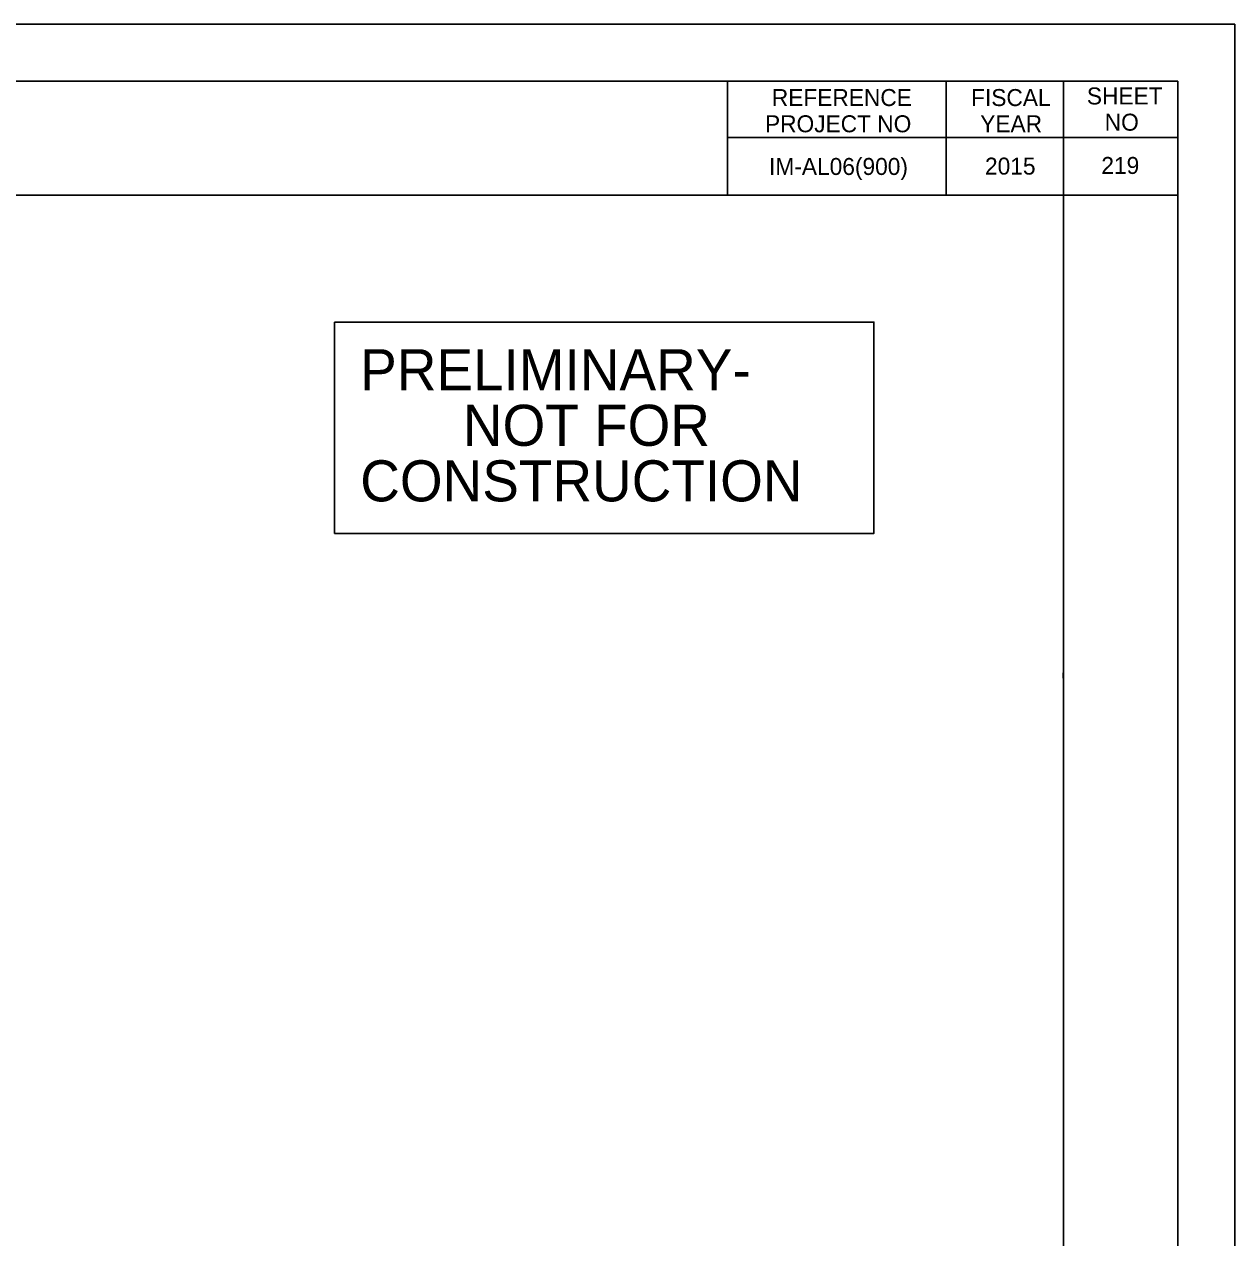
# Model space of a CAD drawing. Extents: x 515543 to 517243, y 660510 to 662861.
# Drawn here: x 516712 to 517243, y 662329 to 662861 of the extents above; entities that cross this region are included whole.
import ezdxf

# ---------------------------------------------------------------- set-up
doc = ezdxf.new("R2010")
doc.units = 0
for name, color, linetype in [('1', 7, 'Continuous'), ('2', 7, 'Continuous'), ('ANNO-SHT', 7, 'Continuous'), ('Level 6', 7, 'Continuous'), ('Level 62', 7, 'Continuous'), ('SHT-BDR', 7, 'Continuous'), ('SHT-BNDRY', 7, 'Continuous')]:
    doc.layers.add(name, color=color, linetype=linetype)

msp = doc.modelspace()

# ---------------------------------------------------------------- linework, layer by layer
at = {"layer": '1'}
msp.add_lwpolyline([(516847.95, 662730.18), (517084.37, 662730.18), (517084.37, 662637.55), (516847.95, 662637.55)], close=True, dxfattribs=at)
at = {"layer": '2'}
msp.add_lwpolyline([(517167.33, 662576.47), (517167.38, 662571.47)], dxfattribs=at)
msp.add_lwpolyline([(517167.33, 662576.47), (517167.38, 662571.47)], dxfattribs=at)
at = {"layer": 'Level 6'}
for p, q in [((517020.23, 662835.72), (517020.23, 662785.77)), ((517116.05, 662810.73), (517116.05, 662835.73)), ((517167.5, 662811.38), (517167.5, 662835.73)), ((517217.52, 662811.02), (517020.23, 662811.02)), ((517116.05, 662810.73), (517116.05, 662785.77)), ((517167.5, 662811.38), (517167.5, 662785.77)), ((517217.52, 662785.77), (517026.28, 662785.77))]:
    msp.add_line(p, q, dxfattribs=at)
at = {"layer": 'Level 62'}
msp.add_lwpolyline([(515542.51, 661760.72), (517242.52, 661760.72), (517242.52, 662860.72), (515542.51, 662860.72)], close=True, dxfattribs=at)
at = {"layer": 'SHT-BDR'}
msp.add_lwpolyline([(515667.5, 661835.77), (517167.5, 661835.77), (517167.5, 662785.77), (515667.5, 662785.77)], close=True, dxfattribs=at)
at = {"layer": 'SHT-BNDRY'}
msp.add_lwpolyline([(515605.01, 661785.72), (517217.52, 661785.72), (517217.52, 662835.72), (515605.01, 662835.72)], close=True, dxfattribs=at)

# ---------------------------------------------------------------- texts
at = {"layer": '1'}
for s, p in [('PRELIMINARY-', (516859.13, 662700.31)), ('NOT FOR', (516904.16, 662675.95)), ('CONSTRUCTION', (516859.16, 662651.6))]:
    msp.add_text(s, height=18, dxfattribs=at).set_placement(p)
at = {"layer": 'ANNO-SHT'}
for s, height, p in [('IM-AL06(900)', 7.4493, (517038.37, 662794.67)), ('2015', 7.449, (517133.04, 662794.83)), ('219', 7.449, (517184.04, 662795.12))]:
    msp.add_text(s, height=height, dxfattribs=at).set_placement(p)
at = {"layer": 'Level 6'}
for s, p in [('REFERENCE', (517039.6, 662824.88)), ('FISCAL', (517126.95, 662824.88)), ('SHEET', (517177.69, 662825.58)), ('PROJECT NO', (517036.6, 662813.38)), ('YEAR', (517130.95, 662813.38)), ('NO', (517185.53, 662814.08))]:
    msp.add_text(s, height=7.442, dxfattribs=at).set_placement(p)

doc.saveas('drawing.dxf')
